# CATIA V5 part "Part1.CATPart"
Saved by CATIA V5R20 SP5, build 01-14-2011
Part number: 花瓶
Material "DS Yellow": density 7860 kg/m3, Young's modulus 2e+11 Pa, Poisson ratio 0.266
Material "DS star": density 1000 kg/m3
Material "DS Light Blue": density 7860 kg/m3, Young's modulus 2e+11 Pa, Poisson ratio 0.266
Bounding box of the stored display mesh (mm): x -58.152 to 48.181, y -37.5 to 37.462, z -0.205 to 147.113
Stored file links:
  E:\scc\Part1.CATPart
  C:\Program Files\Dassault Systemes\B20\intel_a\startup\materials\Catalog.CATMaterial
  C:\Program Files\Dassault Systemes\B20\intel_a\startup\materials\brushed_metal2.jpg
  C:\Program Files\Dassault Systemes\B20\intel_a\startup\materials\brushed_metal1.jpg
  C:\Program Files\Dassault Systemes\B20\intel_a\startup\materials\canvas.jpg
  C:\Program Files\Dassault Systemes\B20\intel_a\startup\materials\alcantara.jpg
  C:\Program Files\Dassault Systemes\B20\intel_a\startup\materials\brown_fiber.jpg
  C:\Program Files\Dassault Systemes\B20\intel_a\startup\materials\brown_fabric_02.jpg
  C:\Program Files\Dassault Systemes\B20\intel_a\startup\materials\honeycomb.jpg
  C:\Program Files\Dassault Systemes\B20\intel_a\startup\materials\blue_fabric_02.jpg
  C:\Program Files\Dassault Systemes\B20\intel_a\startup\materials\canvas.png
  C:\Program Files\Dassault Systemes\B20\intel_a\startup\materials\losange_fabric.jpg
  C:\Program Files\Dassault Systemes\B20\intel_a\startup\materials\concrete.jpg
  C:\Program Files\Dassault Systemes\B20\intel_a\startup\materials\dirty_wall.jpg
  C:\Program Files\Dassault Systemes\B20\intel_a\startup\materials\DS_star.jpg
  C:\Program Files\Dassault Systemes\B20\intel_a\startup\materials\chessboard.jpg
  C:\Program Files\Dassault Systemes\B20\intel_a\startup\materials\summer_sky.jpg
  C:\Program Files\Dassault Systemes\B20\intel_a\startup\materials\raw_polystyren.jpg
  C:\Program Files\Dassault Systemes\B20\intel_a\startup\materials\red_env_512x512.jpg
  C:\Program Files\Dassault Systemes\B20\intel_a\startup\materials\blue_env_512x512.jpg
  C:\Program Files\Dassault Systemes\B20\intel_a\startup\materials\blue_onyx.jpg
  C:\Program Files\Dassault Systemes\B20\intel_a\startup\materials\yellow_env_512x512.jpg
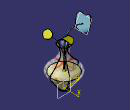
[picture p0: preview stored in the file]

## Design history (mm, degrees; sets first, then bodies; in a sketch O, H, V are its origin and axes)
Body1 (main body), material "DS star"
  Plane1: type Offset, RefPlane xy-plane, Offset 20
  Plane2: type Offset, RefPlane Plane1, Offset 20
  Plane3: type Offset, RefPlane Plane2, Offset 20
  Plane4: type Offset, RefPlane Plane3, Offset 20
  Plane5: type Offset, RefPlane Plane4, Offset 20
  Sketch1 on xy-plane, origin (0, 0, 0), H (1, 0, 0), V (0, 1, 0)
    circle A1 centre (0, 0) radius 11
    radius A1 = 11
  Sketch2 on Plane1, origin (0, 0, 20), H (1, 0, 0), V (0, 1, 0)
    circle A1 centre (0, 0) radius 25
  Sketch3 on Plane2, origin (0, 0, 40), H (1, 0, 0), V (0, 1, 0)
    circle A1 centre (0, 0) radius 37.5
  Sketch4 on Plane3, origin (0, 0, 60), H (1, 0, 0), V (0, 1, 0)
    circle A1 centre (0, 0) radius 21
    radius A1 = 21
  Sketch5 on Plane4, origin (0, 0, 80), H (1, 0, 0), V (0, 1, 0)
    circle A1 centre (0, 0) radius 10
  Sketch6 on Plane5, origin (0, 0, 100), H (1, 0, 0), V (0, 1, 0)
    circle A1 centre (0, 0) radius 15
  Loft1: solid, Sections (Sketch1; Sketch2; Sketch3; Sketch4; Sketch5; Sketch6)
  Shell1: ExtOffset 0, Face face of Loft1, IntOffset 1
Body2, material "DS Yellow"
  Sketch7 on yz-plane, origin (0, 0, 0), H (0, 1, 0), V (0, 0, 1)
    axis line L1 (0, 110.3327) -> (0, -12.441)
    point P1 (0, 110.3327)
    coincidence: P1 V
    vertical: L1 V
  Sketch8 on yz-plane, origin (0, 0, 0), H (0, 1, 0), V (0, 0, 1)
    axis line L1 (0, 110.1581) -> (0, -10.3452)
    point P1 (0, 110.1581)
    point P2 (0, -10.3452)
    point P3 (0, 37.3322)
    line L2 (0, 37.3322) -> (32.0355, 37.3322)
    arc A1 centre (-179.0231, 144.5456) radius 236.7286 from (32.0355, 37.3322) to (9.6626, 1.5835) cw
    line L3 (9.6626, 1.5835) -> (0, 1.5835)
    point P7 (0, 1.5835)
    coincidence: P1 V, P3 L1, A1 P2, P7 L1
    vertical: L1 V
    horizontal: L2 H, L3 H
  Shaft1: profile Sketch8, axis Sketch8.L1, angle 360
  Sketch9 on zx-plane, origin (0, 0, 0), H (-1, 0, 0), V (0, 0, 1)
    construction arc A1 centre (21.3203, 19.0934) radius 28.6202 from (0, 0) to (-3.3686, 33.5699) cw
    construction arc A2 centre (-215.5739, 72.1771) radius 215.6887 from (-3.3686, 33.5699) to (-3.3686, 110.7843) ccw
    construction circle A3 centre (-3.3686, 110.7843) radius 0.1
  Sketch10 on yz-plane, origin (0, 0, 0), H (0, 1, 0), V (0, 0, 1)
    spline S1 through (0, 1.6537) (0, 62.2462) (13.4551, 114.1248)
    point P1 (0, 1.6537)
    point P2 (0, 62.2462)
    coincidence: P1 V, P2 V
  Plane6: type Normal, Curve Sketch10, RefPoint vertex of Sketch10
  Circle1: type CtrRad, Start 0, End 180, Center vertex of Sketch10, Support Plane6, Radius 1, FirstDirection (1, 0, 0)
  Rib1: profile Circle1, centre curve Sketch10
  Sketch11 on Plane6, origin (0, 40.1741, 103.7818), H (1, 0, 0), V (0, -0.9326, 0.361)
    spline S1 through (-5.1678, 37.5177) (-9.3959, 30.0239) (-3.2886, 21.1249) (5.1678, 19.4857) (6.3423, 28.8529) (9.3959, 36.3468) (-5.1678, 37.5177)
    point P1 (-5.1678, 37.5177)
    point P2 (-5.1678, 37.5177)
    coincidence: P1 P2
  Pad1: profile Sketch11, direction (0, 0.361, 0.9326), length 1
  Sketch12 on zx-plane, origin (0, 0, 0), H (-1, 0, 0), V (0, 0, 1)
    spline S1 through (0, 0) (0, 69.3341) (-39.5282, 140.9843)
    point P1 (0, 0)
    point P2 (0, 69.3341)
    coincidence: P1 O, P2 V
  Plane7: type Normal, Curve Sketch12, RefPoint vertex of Sketch12
  Circle2: type CtrRad, Start 0, End 180, Center vertex of Sketch12, Support Plane7, Radius 1, FirstDirection (0, 1, 0)
  Rib2: profile Circle2, centre curve Sketch12
  Sketch13 on Plane7, origin (88.4004, 0, 95.9643), H (0, 1, 0), V (-0.7355, 0, 0.6775)
    spline S1 through (-7.8406, 73.9045) (-11.9476, 61.0628) (4.8537, 57.3405) (9.3341, 66.0878) (0, 73.9045) (-7.8406, 73.9045)
    point P1 (0, 73.9045)
    point P2 (-7.8406, 73.9045)
    point P3 (-7.8406, 73.9045)
    coincidence: P1 V, P2 P3
  Pad2: profile Sketch13, direction (0.6775, 0, 0.7355), length 1
Body3, material "DS Light Blue"
  Sketch14 on zx-plane, origin (0, 0, 0), H (-1, 0, 0), V (0, 0, 1)
    spline S1 through (0, 0) (0, 80) (10, 120) (50, 120)
    point P1 (0, 0)
    point P2 (0, 80)
    coincidence: P1 O, P2 V
  Plane8: type Normal, Curve Sketch14, RefPoint vertex of Sketch14
  Circle3: type CtrRad, Start 0, End 180, Radius 1, Center vertex of Sketch14, Support Plane8, FirstDirection (0, 1, 0)
  Rib3: profile Circle3, centre curve Sketch14
  Sketch15 on Plane8, origin (0.2318, 0, 0.0971), H (0, 1, 0), V (-0.3864, 0, 0.9223)
    spline S1 through (0, 145.8591) (-18.9439, 143.5069) (-18.9439, 129.394) (-10.0308, 116.5877) (14.0871, 117.8945) (16.9708, 134.8823) (10.1548, 150.8247) (0, 145.8591)
    point P1 (0, 145.8591)
    point P2 (0, 145.8591)
    coincidence: P1 V, P2 P1
  Pad3: profile Sketch15, direction (0.9223, 0, 0.3864), length 1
